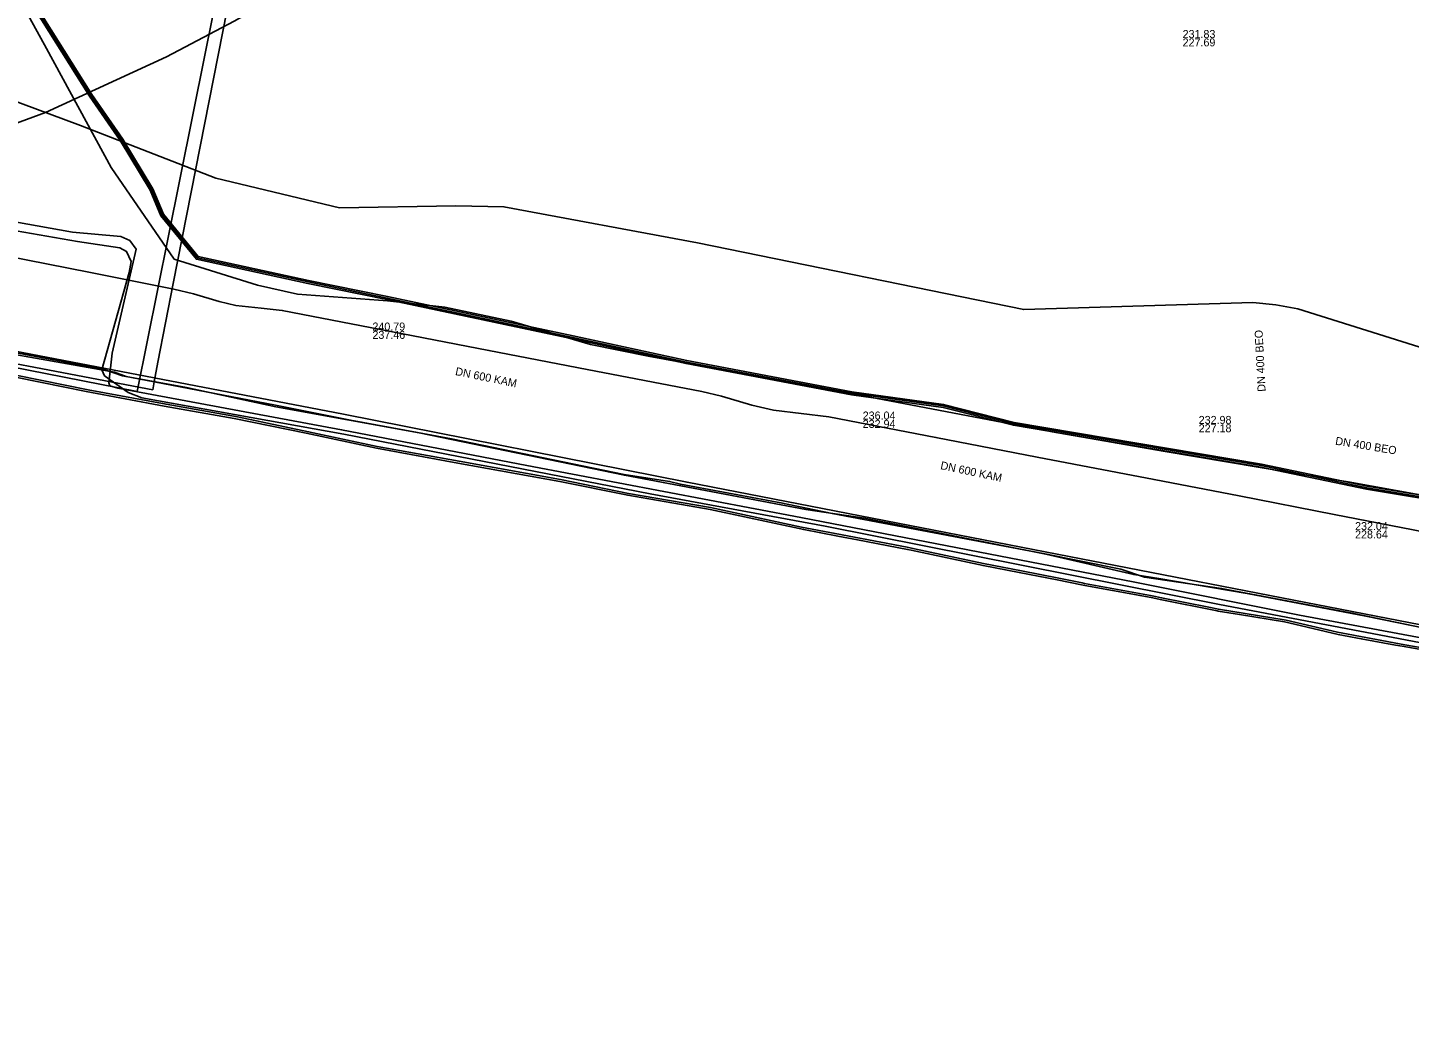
# Model space of a CAD drawing. Extents: x -599951 to -598963, y -1164095 to -1162939.
# Drawn here: x -599594.4 to -599456.3, y -1163169.1 to -1163069.9 of the extents above; entities that cross this region are included whole.
import ezdxf

# ---------------------------------------------------------------- set-up
doc = ezdxf.new("R2010")
doc.units = 0
for name, color, linetype in [('Vrstva 12', 7, 'Continuous'), ('Vrstva 13', 7, 'Continuous'), ('Vrstva 19', 7, 'Continuous'), ('Vrstva 25', 7, 'Continuous'), ('Vrstva 42', 7, 'Continuous'), ('Vrstva 44', 7, 'Continuous'), ('Vrstva 55', 7, 'Continuous'), ('Vrstva 58', 7, 'Continuous')]:
    doc.layers.add(name, color=color, linetype=linetype)

msp = doc.modelspace()

# ---------------------------------------------------------------- linework, layer by layer
at = {"layer": 'Vrstva 12'}
for points in [[(-599580.39, -1163090.87), (-599576.72, -1163072.64), (-599572.49, -1163051.64), (-599556.99, -1163037.17)], [(-599581.77, -1163105.29), (-599581.41, -1163103.32), (-599579.87, -1163095.47), (-599570.88, -1163049.8), (-599562.83, -1163042)], [(-599664.63, -1163105.36), (-599654.17, -1163106.92), (-599649.28, -1163105.66), (-599640.38, -1163099.65), (-599630.69, -1163097), (-599583.49, -1163106.26), (-599580.39, -1163090.87)], [(-599581.77, -1163105.29), (-599584.59, -1163104.75), (-599585.75, -1163104.32), (-599596.28, -1163102.44), (-599611.72, -1163099.35), (-599614, -1163099.46), (-599619.31, -1163098.5), (-599623.09, -1163097.93), (-599633.8, -1163095.75), (-599636.2, -1163098.22), (-599642.46, -1163100.51), (-599647, -1163102)], [(-599581.77, -1163105.29), (-599581.92, -1163106.07), (-599607.48, -1163101.23)], [(-599581.77, -1163105.29), (-599569.65, -1163107.62), (-599562.15, -1163109.11), (-599555.47, -1163110.36), (-599552.06, -1163110.98), (-599534.82, -1163114.55), (-599530.26, -1163115.23), (-599529.19, -1163115.51), (-599519.14, -1163117.36), (-599514.01, -1163118.43), (-599492.94, -1163122.43), (-599485.16, -1163124), (-599482.79, -1163124.8), (-599475.1, -1163125.93), (-599462.05, -1163128.4), (-599450.66, -1163130.75)]]:
    msp.add_lwpolyline(points, dxfattribs=at)
at = {"layer": 'Vrstva 13'}
msp.add_lwpolyline([(-599459.073, -1162939.4), (-599465.76, -1162949.91), (-599471.32, -1162957.71), (-599475.35, -1162963.72), (-599519.14, -1163015.26), (-599531.15, -1163028.03), (-599549.5, -1163049.13), (-599563.156, -1163063.255), (-599573.78, -1163069.24), (-599580.56, -1163072.79), (-599592.642, -1163078.384), (-599610.28, -1163084.85), (-599610.821, -1163085.298), (-599611.357, -1163087.777), (-599613.546, -1163097.928), (-599613.81, -1163099.161), (-599615.07, -1163098.93)], dxfattribs=at)
at = {"layer": 'Vrstva 19'}
msp.add_lwpolyline([(-599616.59, -1163080.56), (-599602.317, -1163074.762), (-599589.155, -1163079.668), (-599575.598, -1163084.941), (-599563.248, -1163087.9), (-599551.627, -1163087.682), (-599546.819, -1163087.795), (-599527.481, -1163091.395), (-599494.862, -1163098.063), (-599471.97, -1163097.364), (-599469.678, -1163097.583), (-599467.49, -1163097.981), (-599449.028, -1163103.799), (-599433.664, -1163109.137), (-599429.505, -1163108.918), (-599428.56, -1163108.95)], dxfattribs=at)
at = {"layer": 'Vrstva 25'}
msp.add_lwpolyline([(-599449.749, -1163130.947), (-599460.681, -1163128.688), (-599472.529, -1163126.446), (-599481.37, -1163124.952), (-599483.873, -1163124.546), (-599492.676, -1163122.519), (-599510.784, -1163118.909), (-599516.643, -1163118.036), (-599534.777, -1163114.618), (-599555.299, -1163110.371), (-599569.62, -1163107.781), (-599578.561, -1163105.855), (-599584.938, -1163104.672), (-599586.873, -1163104.025), (-599610.256, -1163099.613)], dxfattribs=at)
at = {"layer": 'Vrstva 42'}
for p, q in [((-599594.922, -1163067.606), (-599592.525, -1163071.983)), ((-599594.922, -1163067.606), (-599592.525, -1163071.983)), ((-599592.525, -1163071.983), (-599586.079, -1163083.864)), ((-599592.525, -1163071.983), (-599586.079, -1163083.864)), ((-599586.079, -1163083.864), (-599579.793, -1163093.032)), ((-599586.079, -1163083.864), (-599579.793, -1163093.032)), ((-599579.793, -1163093.032), (-599571.436, -1163095.627)), ((-599579.793, -1163093.032), (-599571.436, -1163095.627)), ((-599571.436, -1163095.627), (-599567.439, -1163096.52)), ((-599571.436, -1163095.627), (-599567.439, -1163096.52)), ((-599567.439, -1163096.52), (-599558.474, -1163097.188)), ((-599567.439, -1163096.52), (-599558.474, -1163097.188)), ((-599558.474, -1163097.188), (-599552.73, -1163097.817)), ((-599558.474, -1163097.188), (-599552.73, -1163097.817)), ((-599552.73, -1163097.817), (-599546.085, -1163099.218)), ((-599552.73, -1163097.817), (-599546.085, -1163099.218)), ((-599546.085, -1163099.218), (-599538.153, -1163101.553)), ((-599546.085, -1163099.218), (-599538.153, -1163101.553)), ((-599538.153, -1163101.553), (-599532.421, -1163102.712)), ((-599538.153, -1163101.553), (-599532.421, -1163102.712)), ((-599532.421, -1163102.712), (-599513.179, -1163106.241)), ((-599532.421, -1163102.712), (-599513.179, -1163106.241)), ((-599513.179, -1163106.241), (-599492.04, -1163110.281)), ((-599513.179, -1163106.241), (-599492.04, -1163110.281)), ((-599492.04, -1163110.281), (-599480.951, -1163112.213)), ((-599492.04, -1163110.281), (-599480.951, -1163112.213)), ((-599480.951, -1163112.213), (-599468.262, -1163114.341)), ((-599480.951, -1163112.213), (-599468.262, -1163114.341)), ((-599468.262, -1163114.341), (-599462.431, -1163115.262)), ((-599468.262, -1163114.341), (-599462.431, -1163115.262)), ((-599462.431, -1163115.262), (-599450.168, -1163117.517)), ((-599462.431, -1163115.262), (-599450.168, -1163117.517))]:
    msp.add_line(p, q, dxfattribs=at)
for points in [[(-599614.253, -1163036.379), (-599613.969, -1163039.257), (-599613.476, -1163042.971), (-599610.073, -1163050.561), (-599606.969, -1163055.553), (-599606.712, -1163055.95), (-599600.533, -1163061.628), (-599596.394, -1163064.401), (-599594.353, -1163067.026), (-599588.255, -1163076.753), (-599585.176, -1163081.181), (-599582.184, -1163086.128), (-599581.12, -1163088.698), (-599577.553, -1163093.035), (-599566.411, -1163095.447), (-599558.51, -1163097.067), (-599539.961, -1163100.987), (-599528.61, -1163103.457), (-599512.094, -1163106.568), (-599502.939, -1163107.837), (-599495.901, -1163109.627), (-599471.178, -1163113.807), (-599460.607, -1163116.007), (-599450.989, -1163117.617)], [(-599614.253, -1163036.379), (-599613.969, -1163039.257), (-599613.476, -1163042.971), (-599610.073, -1163050.561), (-599606.969, -1163055.553), (-599606.712, -1163055.95), (-599600.533, -1163061.628), (-599596.394, -1163064.401), (-599594.353, -1163067.026), (-599588.255, -1163076.753), (-599585.176, -1163081.181), (-599582.184, -1163086.128), (-599581.12, -1163088.698), (-599577.553, -1163093.035), (-599566.411, -1163095.447), (-599558.51, -1163097.067), (-599539.961, -1163100.987), (-599528.61, -1163103.457), (-599512.094, -1163106.568), (-599502.939, -1163107.837), (-599495.901, -1163109.627), (-599471.178, -1163113.807), (-599460.607, -1163116.007), (-599450.989, -1163117.617)], [(-599450.931, -1163117.323), (-599460.553, -1163115.713), (-599471.122, -1163113.513), (-599495.839, -1163109.333), (-599502.881, -1163107.543), (-599512.046, -1163106.272), (-599528.55, -1163103.163), (-599539.899, -1163100.693), (-599558.45, -1163096.773), (-599566.349, -1163095.153), (-599577.387, -1163092.765), (-599580.86, -1163088.542), (-599581.916, -1163085.992), (-599584.924, -1163081.019), (-599588.005, -1163076.587), (-599594.107, -1163066.854), (-599596.186, -1163064.179)], [(-599450.931, -1163117.323), (-599460.553, -1163115.713), (-599471.122, -1163113.513), (-599495.839, -1163109.333), (-599502.881, -1163107.543), (-599512.046, -1163106.272), (-599528.55, -1163103.163), (-599539.899, -1163100.693), (-599558.45, -1163096.773), (-599566.349, -1163095.153), (-599577.387, -1163092.765), (-599580.86, -1163088.542), (-599581.916, -1163085.992), (-599584.924, -1163081.019), (-599588.005, -1163076.587), (-599594.107, -1163066.854), (-599596.186, -1163064.179)], [(-599596.186, -1163064.179), (-599594.107, -1163066.854), (-599588.005, -1163076.587), (-599584.924, -1163081.019), (-599581.916, -1163085.992), (-599580.86, -1163088.542), (-599577.387, -1163092.765), (-599566.349, -1163095.153), (-599558.45, -1163096.773), (-599539.899, -1163100.693), (-599528.55, -1163103.163), (-599512.046, -1163106.272), (-599502.881, -1163107.543), (-599495.839, -1163109.333), (-599471.122, -1163113.513), (-599460.553, -1163115.713), (-599450.931, -1163117.323)], [(-599596.186, -1163064.179), (-599594.107, -1163066.854), (-599588.005, -1163076.587), (-599584.924, -1163081.019), (-599581.916, -1163085.992), (-599580.86, -1163088.542), (-599577.387, -1163092.765), (-599566.349, -1163095.153), (-599558.45, -1163096.773), (-599539.899, -1163100.693), (-599528.55, -1163103.163), (-599512.046, -1163106.272), (-599502.881, -1163107.543), (-599495.839, -1163109.333), (-599471.122, -1163113.513), (-599460.553, -1163115.713), (-599450.931, -1163117.323)], [(-599596.29, -1163064.29), (-599594.23, -1163066.94), (-599588.13, -1163076.67), (-599585.05, -1163081.101), (-599582.05, -1163086.06), (-599580.99, -1163088.62), (-599577.47, -1163092.901), (-599566.38, -1163095.3), (-599558.481, -1163096.92), (-599539.93, -1163100.84), (-599528.58, -1163103.31), (-599512.07, -1163106.42), (-599502.91, -1163107.69), (-599495.87, -1163109.48), (-599471.15, -1163113.66), (-599460.581, -1163115.86), (-599450.96, -1163117.47)], [(-599453.72, -1163120.5), (-599463.85, -1163118.54), (-599473.35, -1163116.69), (-599481.84, -1163115.06), (-599493.54, -1163112.8), (-599503.64, -1163110.83), (-599514.35, -1163108.78), (-599519.87, -1163108.1), (-599522.06, -1163107.63), (-599525.08, -1163106.73), (-599527.05, -1163106.26), (-599538.51, -1163104.05), (-599548.32, -1163102.14), (-599558.12, -1163100.24), (-599568.98, -1163098.14), (-599571.09, -1163097.92), (-599573.6, -1163097.65), (-599575.29, -1163097.25), (-599577.83, -1163096.5), (-599579.82, -1163096.01), (-599588.13, -1163094.37), (-599596.76, -1163092.67)], [(-599455.357, -1163132.001), (-599457.043, -1163131.708), (-599457.708, -1163131.586), (-599461.14, -1163130.956), (-599463.45, -1163130.532), (-599467.803, -1163129.506), (-599468.809, -1163129.268), (-599473.303, -1163128.544), (-599475.448, -1163128.198), (-599475.549, -1163128.178), (-599481.233, -1163127.031), (-599481.965, -1163126.883), (-599483.235, -1163126.65), (-599488.771, -1163125.631), (-599489.105, -1163125.565), (-599491.519, -1163125.08), (-599495.319, -1163124.333), (-599498.933, -1163123.645), (-599506.122, -1163122.108), (-599506.487, -1163122.031), (-599511.485, -1163121.076), (-599513.458, -1163120.7), (-599516.861, -1163120.05), (-599526.201, -1163118.044), (-599534.444, -1163116.625), (-599541.235, -1163115.231), (-599551.417, -1163113.4), (-599559.549, -1163111.928), (-599566.577, -1163110.422), (-599573.79, -1163108.934), (-599580.765, -1163107.703), (-599588.573, -1163106.238), (-599593.156, -1163105.321), (-599600.602, -1163103.828)], [(-599449.626, -1163132.791), (-599456.769, -1163131.553), (-599463.498, -1163130.316), (-599468.645, -1163129.102), (-599475.412, -1163128.002), (-599476.374, -1163127.807), (-599481.092, -1163126.855), (-599481.713, -1163126.73), (-599482.21, -1163126.635), (-599483.308, -1163126.433), (-599488.798, -1163125.422), (-599489.039, -1163125.374), (-599491.376, -1163124.905), (-599495.092, -1163124.172), (-599498.882, -1163123.451), (-599505.794, -1163121.974), (-599506.532, -1163121.819), (-599513.722, -1163120.446), (-599517.091, -1163119.801), (-599526.191, -1163117.842), (-599534.374, -1163116.435), (-599541.181, -1163115.038), (-599551.307, -1163113.217), (-599559.496, -1163111.735), (-599566.344, -1163110.268), (-599573.461, -1163108.798), (-599580.59, -1163107.531), (-599588.36, -1163106.075), (-599593.127, -1163105.123), (-599600.556, -1163103.633)]]:
    msp.add_lwpolyline(points, dxfattribs=at)
at = {"layer": 'Vrstva 44'}
msp.add_lwpolyline([(-599599.443, -1163089.526), (-599589.445, -1163091.26), (-599585.196, -1163091.908), (-599584.532, -1163092.252), (-599584.072, -1163093.275), (-599584.263, -1163094.351), (-599587.02, -1163104.081), (-599586.737, -1163104.673), (-599584.367, -1163106.362), (-599582.999, -1163106.897), (-599562.822, -1163110.523), (-599532.196, -1163116.48), (-599514.706, -1163119.714), (-599475.32, -1163127.533), (-599436.546, -1163134.88)], dxfattribs=at)
at = {"layer": 'Vrstva 55'}
msp.add_lwpolyline([(-599618.855, -1163097.599), (-599597.44, -1163101.87), (-599562.87, -1163108.53), (-599528.51, -1163115.32), (-599493.94, -1163122.04), (-599459.65, -1163128.7), (-599425.29, -1163135.35), (-599390.79, -1163142.01), (-599379.04, -1163144.18), (-599370.08, -1163145.68), (-599333.88, -1163152.87), (-599287.5, -1163161.7), (-599253.07, -1163168.09), (-599247.97, -1163169.04), (-599246.945, -1163169.092), (-599247.03, -1163167.178), (-599245.243, -1163166.795)], dxfattribs=at)
at = {"layer": 'Vrstva 58'}
msp.add_lwpolyline([(-599752.946, -1163056.655), (-599739.506, -1163059.075), (-599723.286, -1163062.295), (-599708.496, -1163065.135), (-599689.456, -1163068.595), (-599664.066, -1163073.415), (-599653.826, -1163076.325), (-599629.566, -1163083.125), (-599618.646, -1163085.265), (-599601.496, -1163088.275), (-599589.936, -1163090.325), (-599585.106, -1163090.775), (-599584.226, -1163091.175), (-599583.576, -1163092.035), (-599585.966, -1163102.435), (-599586.306, -1163105.375), (-599586.196, -1163105.675), (-599585.406, -1163105.925), (-599563.046, -1163110.065), (-599544.516, -1163113.655), (-599517.146, -1163118.855), (-599483.776, -1163125.315), (-599467.296, -1163128.595), (-599449.626, -1163131.895)], dxfattribs=at)
msp.add_lwpolyline([(-599752.946, -1163056.655), (-599739.506, -1163059.075), (-599723.286, -1163062.295), (-599708.496, -1163065.135), (-599689.456, -1163068.595), (-599664.066, -1163073.415), (-599653.826, -1163076.325), (-599629.566, -1163083.125), (-599618.646, -1163085.265), (-599601.496, -1163088.275), (-599589.936, -1163090.325), (-599585.106, -1163090.775), (-599584.226, -1163091.175), (-599583.576, -1163092.035), (-599585.966, -1163102.435), (-599586.306, -1163105.375), (-599586.196, -1163105.675), (-599585.406, -1163105.925), (-599563.046, -1163110.065), (-599544.516, -1163113.655), (-599517.146, -1163118.855), (-599483.776, -1163125.315), (-599467.296, -1163128.595), (-599449.626, -1163131.895)], dxfattribs=at)

# ---------------------------------------------------------------- texts
at = {"layer": 'Vrstva 12'}
for s, p in [('231.83', (-599478.991, -1163070.93)), ('227.69', (-599478.991, -1163071.762)), ('240.79', (-599559.964, -1163100.16)), ('237.46', (-599559.964, -1163100.992)), ('236.04', (-599510.965, -1163109.052)), ('232.94', (-599510.965, -1163109.884)), ('232.98', (-599477.384, -1163109.491)), ('227.18', (-599477.384, -1163110.323)), ('232.04', (-599461.755, -1163120.1)), ('228.64', (-599461.755, -1163120.932))]:
    msp.add_text(s, height=0.8, dxfattribs=at).set_placement(p)
for s, rotation, p in [('DN 400 BEO', 92.87646, (-599470.695, -1163106.254)), ('DN 600 KAM', 348.40896, (-599551.734, -1163104.593)), ('DN 400 BEO', 350.72546, (-599463.776, -1163111.554)), ('DN 600 KAM', 348.06453, (-599503.248, -1163113.992))]:
    msp.add_text(s, height=0.8, rotation=rotation, dxfattribs=at).set_placement(p)

doc.saveas('drawing.dxf')
